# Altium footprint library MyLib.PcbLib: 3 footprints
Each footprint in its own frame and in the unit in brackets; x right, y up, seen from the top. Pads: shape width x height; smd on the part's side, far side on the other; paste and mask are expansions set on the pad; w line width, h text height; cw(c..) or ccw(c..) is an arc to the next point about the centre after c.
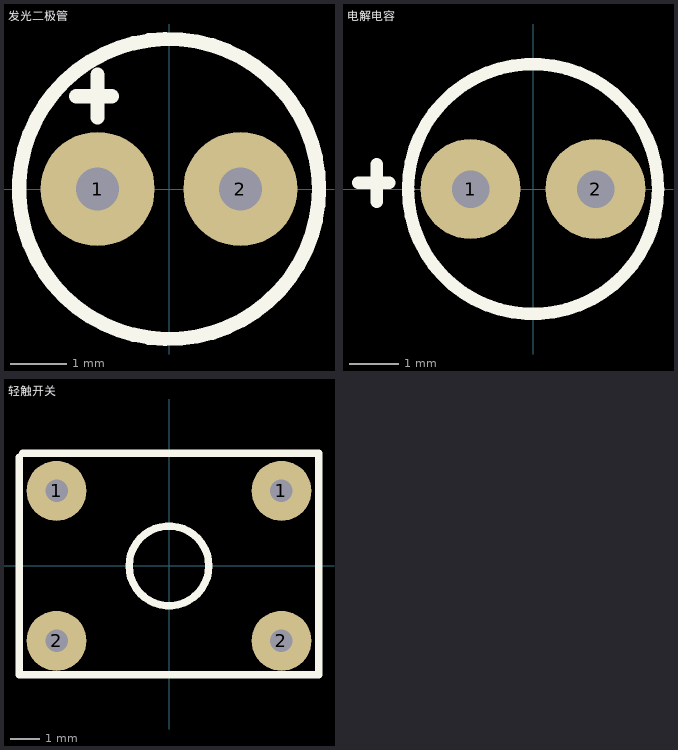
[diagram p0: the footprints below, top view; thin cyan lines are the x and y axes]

## 发光二极管 [mil]
pads (2):
  round 80 hole 30: 1(-50,0) 2(50,0)
Top Overlay:
  circle w10: c0,0 r105
  lines w10: -65,65 -40,65 ; -50,50 -50,80

## 电解电容 [mil]
pads (2):
  round 80 hole 30: 1(-50,0) 2(50,0)
Top Overlay:
  circle w10: c0,0 r100
  lines w10: -140,5 -115,5 ; -125,-10 -125,20

## 轻触开关 [mil]
pads (4):
  round 80 hole 30: 1(-150,100) 1(150,100) 2(-150,-100) 2(150,-100)
Top Overlay:
  circle w10: c0,0 r53.15
  lines w10: -200,145 -200,-145 200,-145 200,150 -195,150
